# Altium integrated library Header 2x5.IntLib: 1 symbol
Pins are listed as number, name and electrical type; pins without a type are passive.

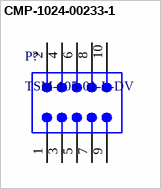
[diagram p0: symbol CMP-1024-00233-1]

## CMP-1024-00233-1
designator P?, comment TSM-105-01-L-DV
0.025" SQ Post Header, Surface Mount, Vertical, -55 to 125 degC, 2.54 mm Pitch, 10-Pin, Male, RoHS; Manufacturer: Samtec; Pitch: 2.54 mm
footprint SMTC-TSM-105-01-X-DV (Double Row Gullwing ASM, 2x5 Pins, Vertical, 2.54mm Pitch, Male)
pins: 1, 2, 3, 4, 5, 6, 7, 8, 9, 10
